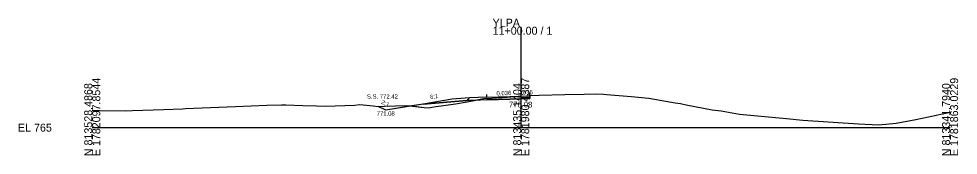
# Model space of a CAD drawing. Extents: x -76 to 1303, y -10 to 9544.
# Drawn here: x -25.7 to 302.8, y 990.3 to 1038.2 of the extents above; entities that cross this region are included whole.
import ezdxf

# ---------------------------------------------------------------- set-up
doc = ezdxf.new("R2010")
doc.units = 0
for name, color, linetype in [('Exist Cross Section Cell', 7, 'Continuous'), ('Exist XS Center Line Elevation Label', 7, 'Continuous'), ('Exist XS Ground Line', 7, 'Continuous'), ('Prop XS Ditch Slope Text', 7, 'Continuous'), ('Prop XS Ditch Standard Text', 7, 'Continuous'), ('Prop XS Dump Level', 7, 'Continuous'), ('Prop XS Earthwork Shape', 7, 'Continuous'), ('Prop XS EOT Tick Mark', 7, 'Continuous'), ('Prop XS Finish Grade', 7, 'Continuous'), ('Prop XS Finish Grade Earthwork', 7, 'Continuous'), ('Prop XS Finish Grade Paved Shoulder', 7, 'Continuous'), ('Prop XS Finish Grade Pavement', 7, 'Continuous'), ('Prop XS Pvmt Edge Slope', 7, 'Continuous'), ('Prop XS SE Text', 7, 'Continuous'), ('Prop XS Side Slope Text', 7, 'Continuous'), ('Prop XS SS Elevation Text', 7, 'Continuous'), ('Prop XS Subgrade Earthwork', 7, 'Continuous'), ('Scratch_Level_3', 7, 'Continuous')]:
    doc.layers.add(name, color=color, linetype=linetype)

msp = doc.modelspace()

# ---------------------------------------------------------------- linework, layer by layer
at = {"layer": 'Exist Cross Section Cell'}
for p, q in [((150, 1000), (150, 1035.4)), ((0, 1000), (150, 1000)), ((150, 1000), (300, 1000))]:
    msp.add_line(p, q, dxfattribs=at)
at = {"layer": 'Exist XS Ground Line'}
for p, q in [((127.05, 1008.33), (131.12, 1009.09)), ((131.12, 1009.09), (136.86, 1010.2)), ((136.86, 1010.2), (139.74, 1010.3)), ((139.74, 1010.3), (145.07, 1010.63)), ((145.07, 1010.63), (148.92, 1011.02)), ((148.92, 1011.02), (150, 1011.08)), ((150, 1011.08), (151.92, 1011.18)), ((151.92, 1011.18), (153, 1011.24)), ((153, 1011.24), (156.25, 1011.34)), ((156.25, 1011.34), (165.25, 1011.6)), ((165.25, 1011.6), (172, 1011.71)), ((172, 1011.71), (176.41, 1011.8)), ((176.41, 1011.8), (178.74, 1011.71)), ((178.74, 1011.71), (179.96, 1011.66)), ((179.96, 1011.66), (188.51, 1010.87)), ((188.51, 1010.87), (194.69, 1010.3)), ((194.69, 1010.3), (203.81, 1008.73)), ((203.81, 1008.73), (205.73, 1008.43)), ((0, 1006.02), (2.65, 1006.02)), ((2.65, 1006.02), (11.8, 1005.95)), ((11.8, 1005.95), (14.02, 1006.04)), ((14.02, 1006.04), (24.93, 1006.4)), ((24.93, 1006.4), (31.51, 1006.62)), ((31.51, 1006.62), (32.63, 1006.66)), ((32.63, 1006.66), (50.05, 1007.41)), ((50.05, 1007.41), (61.1, 1007.83)), ((61.1, 1007.83), (66.21, 1008)), ((66.21, 1008), (67.7, 1007.97)), ((67.7, 1007.97), (73.69, 1007.73)), ((73.69, 1007.73), (78.4, 1007.59)), ((78.4, 1007.59), (81.4, 1007.57)), ((81.4, 1007.57), (91.83, 1007.91)), ((91.83, 1007.91), (93.62, 1008.15)), ((93.62, 1008.15), (98.19, 1007.63)), ((98.19, 1007.63), (99.93, 1007.41)), ((99.93, 1007.41), (102.19, 1007.56)), ((102.19, 1007.56), (109.89, 1007.8)), ((109.89, 1007.8), (116.11, 1007.11)), ((116.11, 1007.11), (117.51, 1006.97)), ((117.51, 1006.97), (119.51, 1007.26)), ((119.51, 1007.26), (127.05, 1008.33)), ((205.73, 1008.43), (207.65, 1008.02)), ((207.65, 1008.02), (216.74, 1006.27)), ((216.74, 1006.27), (219.96, 1005.85)), ((219.96, 1005.85), (226.31, 1004.74)), ((292.46, 1003.77), (300, 1005.37)), ((226.31, 1004.74), (242.78, 1003.23)), ((242.78, 1003.23), (248.52, 1002.66)), ((248.52, 1002.66), (268, 1001.32)), ((281.15, 1001.56), (287.99, 1002.91)), ((287.99, 1002.91), (292.46, 1003.77)), ((268, 1001.32), (275.12, 1000.98)), ((275.12, 1000.98), (281.15, 1001.56))]:
    msp.add_line(p, q, dxfattribs=at)
at = {"layer": 'Prop XS Dump Level'}
for p, q in [((138, 1010.64), (150, 1011.08)), ((150, 1011.08), (153.04, 1011.19))]:
    msp.add_line(p, q, dxfattribs=at)
at = {"layer": 'Prop XS Earthwork Shape'}
for points in [[(115.74, 1008.25), (111.77, 1007.59), (116.11, 1007.11), (117.51, 1006.97), (119.51, 1007.26), (127.05, 1008.33), (131.12, 1009.09), (133.57, 1009.57), (130.95, 1009.47)], [(133.57, 1009.57), (136.86, 1010.2), (139.74, 1010.3), (145.07, 1010.63), (148.92, 1011.02), (150, 1011.08), (151.92, 1011.18), (153, 1011.24), (153.04, 1011.24), (153.04, 1010.27), (150.03, 1010.16), (138.03, 1009.73)], [(102.71, 1006.08), (100.04, 1007.42), (102.19, 1007.56), (109.89, 1007.8), (111.77, 1007.59)]]:
    msp.add_lwpolyline(points, close=True, dxfattribs=at)
at = {"layer": 'Prop XS EOT Tick Mark'}
for p, q in [((153.04, 1011.19), (153.04, 1012.19)), ((138, 1010.64), (138, 1011.64))]:
    msp.add_line(p, q, dxfattribs=at)
at = {"layer": 'Prop XS Finish Grade'}
for p, q in [((125.85, 1009.94), (115.74, 1008.25)), ((131.9, 1010.42), (125.85, 1009.94))]:
    msp.add_line(p, q, dxfattribs=at)
at = {"layer": 'Prop XS Finish Grade Earthwork'}
for p, q in [((102.71, 1006.08), (100.04, 1007.42)), ((115.74, 1008.25), (102.71, 1006.08))]:
    msp.add_line(p, q, dxfattribs=at)
at = {"layer": 'Prop XS Finish Grade Paved Shoulder'}
msp.add_line((138, 1010.64), (131.9, 1010.42), dxfattribs=at)
at = {"layer": 'Prop XS Finish Grade Pavement'}
for p, q in [((138, 1010.64), (150, 1011.08)), ((150, 1011.08), (153.04, 1011.19))]:
    msp.add_line(p, q, dxfattribs=at)
at = {"layer": 'Prop XS Pvmt Edge Slope'}
msp.add_line((131.9, 1010.42), (130.95, 1009.47), dxfattribs=at)
at = {"layer": 'Prop XS Subgrade Earthwork'}
for p, q in [((130.95, 1009.47), (115.74, 1008.25)), ((138.03, 1009.73), (130.95, 1009.47)), ((138.03, 1009.73), (150.03, 1010.16)), ((150.03, 1010.16), (153.04, 1010.27)), ((153.04, 1010.27), (153.04, 1011.24))]:
    msp.add_line(p, q, dxfattribs=at)
at = {"layer": 'Scratch_Level_3'}
for p, q in [((125.85, 1009.94), (115.74, 1008.25)), ((115.74, 1008.25), (130.95, 1009.47)), ((131.9, 1010.42), (125.85, 1009.94)), ((130.95, 1009.47), (131.9, 1010.42))]:
    msp.add_line(p, q, dxfattribs=at)

# ---------------------------------------------------------------- texts
at = {"layer": 'Exist Cross Section Cell'}
for s, p in [('YLPA', (140, 1035.4)), ('11+00.00 / 1', (140, 1032.6)), ('EL 765', (-26, 998.6))]:
    msp.add_text(s, height=2.8, dxfattribs=at).set_placement(p)
for s, p in [('N 813528.4868', (0, 990)), ('E 1782097.8544', (2.8, 990)), ('N 813435.1404', (150, 990)), ('E 1781980.4387', (152.8, 990)), ('N 813341.7940', (300, 990)), ('E 1781863.0229', (302.8, 990))]:
    msp.add_text(s, height=2.8, rotation=90, dxfattribs=at).set_placement(p)
at = {"layer": 'Exist XS Center Line Elevation Label'}
msp.add_text('776.08', height=2, dxfattribs=at).set_placement((145.73, 1007.08))
at = {"layer": 'Prop XS Ditch Slope Text'}
msp.add_text('6:1', height=1.5, rotation=9.4623, dxfattribs=at).set_placement((118.25, 1009.96))
at = {"layer": 'Prop XS Ditch Standard Text'}
msp.add_text('771.08', height=1.5, dxfattribs=at).set_placement((99.46, 1004.21))
at = {"layer": 'Prop XS Dump Level'}
msp.add_text('Case4', height=0.04, dxfattribs=at).set_placement((125.85, 1010.03))
at = {"layer": 'Prop XS SE Text'}
for p in [(141.39, 1011.27), (148.91, 1011.54)]:
    msp.add_text('0.036', height=1.5, rotation=2.0805, dxfattribs=at).set_placement(p)
at = {"layer": 'Prop XS Side Slope Text'}
msp.add_text('2:1', height=1.5, rotation=333.4349, dxfattribs=at).set_placement((100.92, 1008.47))
at = {"layer": 'Prop XS SS Elevation Text'}
msp.add_text('S.S. 772.42', height=1.5, dxfattribs=at).set_placement((96.06, 1010.18))

doc.saveas('drawing.dxf')
